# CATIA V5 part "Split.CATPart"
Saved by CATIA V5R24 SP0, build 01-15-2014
Part number: Part1
Bounding box of the stored display mesh (mm): x -30 to 480, y -129.222 to 80, z -50 to 70
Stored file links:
  E:\Desktop_RNH\학부 실습 강의자료 (CAD)\툴바예제\4 GSD\Operations\Split2.CATPart
  E:\users\spu\Gsd R10\TrimKeepRemove.CATPart
  C:\Documents and Settings\spu\Local Settings\Temp\r.notes.data\GSMSplitMultisel.CATPart
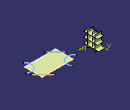
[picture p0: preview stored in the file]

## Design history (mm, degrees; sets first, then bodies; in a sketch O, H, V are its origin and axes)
SheetMetalParameters1: Thickness 2, BendRadius 4, KFactor 0.400515 {= log(min(100,max(20*SheetMetalParameters1.BendRadius,SheetMetalParameters1.Thickness)/SheetMetalParameters1.Thickness))/log(100)/2}, ReliefRadialLength 1, ReliefAxialLength 2, WallPerLength 50, MinimumBendRadius 0
Set1 "Geometrical Set.2"
  Sketch1 on xy-plane, origin (0, 0, 0), H (1, 0, 0), V (0, 1, 0)
    line L1 (-120, 40) -> (-120, -100)
    vertical: L1 V
  Extrude1 "Extrude.1": Element1 Sketch1, Lim1 566, Lim2 -320, Direction yz-plane
  Sketch2 on xy-plane, origin (0, 0, 0), H (1, 0, 0), V (0, 1, 0)
    arc A1 centre (449.9488, -89.6111) radius 49.7203 from (419.8977, -129.2222) to (480, -50) cw
  Sketch3 on , origin (0, 0, 0), H (1, 0, 0), V (0, 1, 0)
    arc A1 centre (205, 50) radius 54.0833 from (250, 80) to (160, 20) cw
  Sketch4 on xy-plane, origin (0, 0, 0), H (1, 0, 0), V (0, 1, 0)
    line L1 (180, -40) -> (260, -120)
  Sketch5 on xy-plane, origin (0, 0, 0), H (1, 0, 0), V (0, 1, 0)
    line L1 (380, 70) -> (470, -20)
Set2 "MultiSplit"
  Line1: type PtPt, FirstPoint {point type OnPlane, Support yz-plane, H -60, V 50, Direction (0, 1, 0)}, Support yz-plane, SecondPoint {point type OnPlane, Support yz-plane, H 50, V 50, Direction (0, 1, 0)}
  Line2: type PtPt, FirstPoint {point type OnPlane, Support yz-plane, H -60, V -30, Direction (0, 1, 0)}, Support yz-plane, SecondPoint {point type OnPlane, Support yz-plane, H 60, V -30, Direction (0, 1, 0)}
  Line3: type PtPt, FirstPoint {point type OnPlane, Support yz-plane, H -30, V 70, Direction (0, 1, 0)}, Support yz-plane, SecondPoint {point type OnPlane, Support yz-plane, H -30, V -50, Direction (0, 1, 0)}
  Line4: type PtPt, FirstPoint {point type OnPlane, Support yz-plane, H 30, V 70, Direction (0, 1, 0)}, Support yz-plane, SecondPoint {point type OnPlane, Support yz-plane, H 30, V -50, Direction (0, 1, 0)}
  Line5: type PtPt, FirstPoint {point type OnPlane, Support yz-plane, H 0, V -50, Direction (0, 1, 0)}, Support yz-plane, SecondPoint {point type OnPlane, Support yz-plane, H 0, V 70, Direction (0, 1, 0)}
  Line6: type PtPt, FirstPoint {point type OnPlane, Support yz-plane, H 50, V 10, Direction (0, 1, 0)}, Support yz-plane, SecondPoint {point type OnPlane, Support yz-plane, H -60, V 10, Direction (0, 1, 0)}
  Extrude2: Element1 Line1, Lim1 20, Lim2 30, Direction (1, 0, 0)
  Extrude3: Element1 Line6, Lim1 20, Lim2 30, Direction (1, 0, 0)
  Extrude4: Element1 Line2, Lim1 20, Lim2 30, Direction (1, 0, 0)
  Extrude5: Element1 Line3, Lim1 20, Lim2 30, Direction (1, 0, 0)
  Extrude6: Element1 Line5, Lim1 10, Lim2 20, Direction (1, 0, 0)
  Extrude7: Element1 Line4, Lim1 20, Lim2 30, Direction (1, 0, 0)
Body1 (main body)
